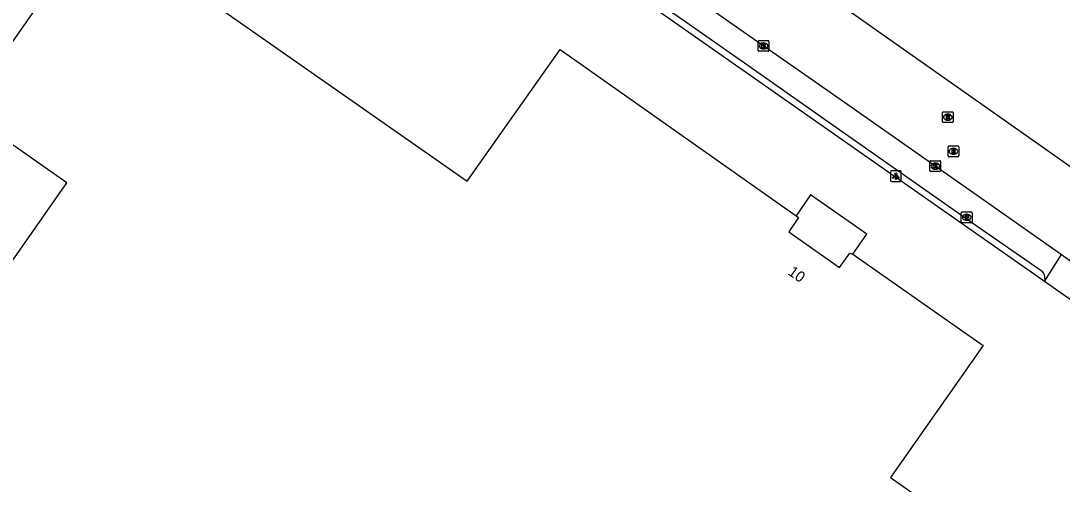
# Model space of a CAD drawing. Extents: x 155018 to 156648, y 383980 to 385733.
# Drawn here: x 155235.9 to 155332.5, y 384821.5 to 384864.6 of the extents above; entities that cross this region are included whole.
import ezdxf

# ---------------------------------------------------------------- set-up
doc = ezdxf.new("R2010")
doc.units = 0
for name, color, linetype in [('IMGEO_Brandkraan', 7, 'Continuous'), ('IMGEO_Kolk', 7, 'Continuous'), ('IMGEO_Lichtpunt', 7, 'Continuous'), ('IMGEO_Pand', 7, 'Continuous'), ('IMGEO_Pand_nummerreeks', 7, 'Continuous'), ('IMGEO_Pand_overbouw', 7, 'Continuous'), ('IMGEO_Rijbaan_lokaal_gesloten', 7, 'Continuous'), ('IMGEO_Rijbaan_lokaal_open', 7, 'Continuous'), ('IMGEO_Rioolput', 7, 'Continuous'), ('IMGEO_Voetpad_open', 7, 'Continuous')]:
    doc.layers.add(name, color=color, linetype=linetype)

msp = doc.modelspace()

# ---------------------------------------------------------------- linework, layer by layer
at = {"layer": 'IMGEO_Brandkraan'}
for p, q in [((155323.18, 384845.9), (155323.18, 384846.752)), ((155323.255, 384846.826), (155324.107, 384846.826)), ((155323.668, 384846.606), (155323.693, 384846.606)), ((155324.181, 384846.752), (155324.181, 384845.9)), ((155324.107, 384845.826), (155323.255, 384845.826)), ((155323.691, 384846.046), (155323.666, 384846.046))]:
    msp.add_line(p, q, dxfattribs=at)
for points in [[(155323.18, 384845.9), (155323.18, 384846.752)], [(155323.255, 384846.826), (155324.107, 384846.826)], [(155324.181, 384846.752), (155324.181, 384845.9)], [(155324.107, 384845.826), (155323.255, 384845.826)], [(155323.528, 384846.526), (155323.528, 384846.126), (155323.741, 384846.126)], [(155323.759, 384846.526), (155323.528, 384846.526)], [(155323.707, 384846.445), (155323.653, 384846.445), (155323.653, 384846.369)], [(155323.653, 384846.369), (155323.706, 384846.369)], [(155323.715, 384846.293), (155323.653, 384846.293), (155323.653, 384846.212)], [(155323.653, 384846.212), (155323.715, 384846.212)]]:
    msp.add_lwpolyline(points, dxfattribs=at)
for centre, radius, start, end in [((155323.257, 384846.75), 0.0765, 91.55205, 178.44795), ((155323.257, 384846.75), 0.0765, 91.55205, 178.44795), ((155324.105, 384846.75), 0.0765, 1.55205, 88.44795), ((155324.105, 384846.75), 0.0765, 1.55205, 88.44795), ((155323.257, 384845.902), 0.0765, 181.55205, 268.44795), ((155323.257, 384845.902), 0.0765, 181.55205, 268.44795), ((155323.708, 384846.407), 0.0379, 267.82845, 90.93552), ((155323.716, 384846.252), 0.0404, 269.87594, 90.50774), ((155323.747, 384846.377), 0.251, 268.66757, 293.53466), ((155323.763, 384846.381), 0.145, 59.4692, 91.53667), ((155323.788, 384846.428), 0.0922, 285.51372, 58.15012), ((155323.793, 384846.236), 0.105, 301.31148, 78.98903), ((155324.105, 384845.902), 0.0765, 271.55205, 358.44795), ((155324.105, 384845.902), 0.0765, 271.55205, 358.44795)]:
    msp.add_arc(centre, radius, start, end, dxfattribs=at)
for centre, major_axis, ratio, start_param, end_param in [((155323.667, 384846.326), (-0.387, 0.002), 0.722429, 4.712389, 7.853982), ((155323.692, 384846.326), (-0.39, 0.002), 0.717154, 1.570796, 4.712389)]:
    msp.add_ellipse(centre, major_axis=major_axis, ratio=ratio, start_param=start_param, end_param=end_param, dxfattribs=at)
at = {"layer": 'IMGEO_Kolk'}
for p, q in [((155304.331, 384861.82), (155304.331, 384862.672)), ((155304.406, 384862.746), (155305.258, 384862.746)), ((155304.819, 384862.526), (155304.844, 384862.526)), ((155305.332, 384862.672), (155305.332, 384861.82)), ((155305.258, 384861.746), (155304.406, 384861.746)), ((155304.842, 384861.966), (155304.817, 384861.966)), ((155320.265, 384850.655), (155320.265, 384851.507)), ((155320.34, 384851.581), (155321.192, 384851.581)), ((155321.266, 384851.507), (155321.266, 384850.655)), ((155321.192, 384850.581), (155320.34, 384850.581)), ((155320.776, 384850.801), (155320.751, 384850.801)), ((155320.753, 384851.361), (155320.778, 384851.361))]:
    msp.add_line(p, q, dxfattribs=at)
for points in [[(155304.331, 384861.82), (155304.331, 384862.672)], [(155304.406, 384862.746), (155305.258, 384862.746)], [(155304.652, 384862.446), (155304.775, 384862.446), (155304.775, 384862.295), (155304.905, 384862.446), (155305.069, 384862.446), (155304.923, 384862.295), (155305.076, 384862.046), (155304.924, 384862.046), (155304.839, 384862.21), (155304.775, 384862.143), (155304.775, 384862.046), (155304.652, 384862.046), (155304.652, 384862.446)], [(155305.332, 384862.672), (155305.332, 384861.82)], [(155305.258, 384861.746), (155304.406, 384861.746)], [(155320.265, 384850.655), (155320.265, 384851.507)], [(155320.34, 384851.581), (155321.192, 384851.581)], [(155321.266, 384851.507), (155321.266, 384850.655)], [(155321.192, 384850.581), (155320.34, 384850.581)], [(155320.586, 384851.281), (155320.709, 384851.281), (155320.709, 384851.13), (155320.839, 384851.281), (155321.003, 384851.281), (155320.857, 384851.13), (155321.01, 384850.881), (155320.858, 384850.881), (155320.773, 384851.045), (155320.709, 384850.978), (155320.709, 384850.881), (155320.586, 384850.881), (155320.586, 384851.281)]]:
    msp.add_lwpolyline(points, dxfattribs=at)
for centre, start, end in [((155304.408, 384862.67), 91.55205, 178.44795), ((155304.408, 384862.67), 91.55205, 178.44795), ((155305.256, 384862.67), 1.55205, 88.44795), ((155305.256, 384862.67), 1.55205, 88.44795), ((155304.408, 384861.822), 181.55205, 268.44795), ((155304.408, 384861.822), 181.55205, 268.44795), ((155305.256, 384861.822), 271.55205, 358.44795), ((155305.256, 384861.822), 271.55205, 358.44795), ((155320.342, 384851.505), 91.55205, 178.44795), ((155320.342, 384851.505), 91.55205, 178.44795), ((155321.19, 384851.505), 1.55205, 88.44795), ((155321.19, 384851.505), 1.55205, 88.44795), ((155320.342, 384850.657), 181.55205, 268.44795), ((155320.342, 384850.657), 181.55205, 268.44795), ((155321.19, 384850.657), 271.55205, 358.44795), ((155321.19, 384850.657), 271.55205, 358.44795)]:
    msp.add_arc(centre, 0.0765, start, end, dxfattribs=at)
for centre, major_axis, ratio, start_param, end_param in [((155304.818, 384862.246), (-0.387, 0.002), 0.722429, 4.712389, 7.853982), ((155304.843, 384862.246), (-0.39, 0.002), 0.717154, 1.570796, 4.712389), ((155320.752, 384851.081), (-0.387, 0.002), 0.722429, 4.712389, 7.853982), ((155320.777, 384851.081), (-0.39, 0.002), 0.717154, 1.570796, 4.712389)]:
    msp.add_ellipse(centre, major_axis=major_axis, ratio=ratio, start_param=start_param, end_param=end_param, dxfattribs=at)
at = {"layer": 'IMGEO_Lichtpunt'}
for p, q in [((155316.6, 384850.558), (155316.6, 384849.751)), ((155316.6, 384850.558), (155316.6, 384849.751)), ((155317.502, 384850.653), (155316.694, 384850.653)), ((155317.502, 384850.653), (155316.694, 384850.653)), ((155317.596, 384849.751), (155317.596, 384850.558)), ((155317.596, 384849.751), (155317.596, 384850.558)), ((155316.694, 384849.657), (155317.502, 384849.657)), ((155316.694, 384849.657), (155317.502, 384849.657))]:
    msp.add_line(p, q, dxfattribs=at)
for points in [[(155316.974, 384850.222), (155317.013, 384850.194), (155316.825, 384849.932), (155316.787, 384849.959), (155316.974, 384850.222)], [(155317.076, 384850.174), (155317.123, 384850.174), (155317.123, 384849.852), (155317.076, 384849.852), (155317.076, 384850.174)], [(155317.186, 384850.194), (155317.224, 384850.221), (155317.411, 384849.959), (155317.372, 384849.931), (155317.186, 384850.194)]]:
    msp.add_lwpolyline(points, dxfattribs=at)
msp.add_circle((155317.099, 384850.356), 0.0994, dxfattribs=at)
for centre, start, end in [((155316.694, 384850.558), 90, 180), ((155316.694, 384850.558), 90, 180), ((155317.502, 384850.558), 0, 90), ((155317.502, 384850.558), 0, 90), ((155316.694, 384849.751), 180, 270), ((155316.694, 384849.751), 180, 270), ((155317.502, 384849.751), 270, 0), ((155317.502, 384849.751), 270, 360)]:
    msp.add_arc(centre, 0.0946, start, end, dxfattribs=at)
at = {"layer": 'IMGEO_Pand'}
msp.add_lwpolyline([(155307.854, 384846.467), (155308.084, 384846.304), (155307.162, 384844.985), (155311.873, 384841.65), (155312.842, 384843.004), (155313.123, 384842.891), (155325.2, 384834.412), (155316.62, 384822.15), (155331.369, 384811.803), (155328.502, 384807.708), (155294.79, 384759.56), (155206.342, 384821.5), (155218.64, 384839.075), (155228.194, 384832.391), (155240.179, 384849.519), (155230.625, 384856.203), (155240.044, 384869.665), (155242.91, 384873.761), (155277.333, 384849.672), (155285.969, 384861.914), (155307.854, 384846.467)], dxfattribs=at)
at = {"layer": 'IMGEO_Pand_overbouw'}
msp.add_lwpolyline([(155307.854, 384846.467), (155308.084, 384846.304), (155307.162, 384844.985), (155311.873, 384841.65), (155312.842, 384843.004), (155313.123, 384842.891), (155314.41, 384844.769), (155309.184, 384848.411)], close=True, dxfattribs=at)
at = {"layer": 'IMGEO_Rijbaan_lokaal_gesloten'}
for points in [[(155282.705, 384877.749), (155304.661, 384862.364), (155312.349, 384857.014), (155325.715, 384847.641), (155332.492, 384842.858)], [(155339.386, 384846.829), (155338.759, 384847.187), (155308.812, 384868.307)], [(155332.492, 384842.858), (155336.825, 384839.821)]]:
    msp.add_lwpolyline(points, dxfattribs=at)
at = {"layer": 'IMGEO_Rijbaan_lokaal_open'}
for points in [[(155330.905, 384840.366), (155332.492, 384842.858)], [(155335.262, 384837.311), (155330.905, 384840.366)]]:
    msp.add_lwpolyline(points, dxfattribs=at)
at = {"layer": 'IMGEO_Rioolput'}
for p, q in [((155321.431, 384855.202), (155321.431, 384856.054)), ((155321.506, 384856.128), (155322.358, 384856.128)), ((155321.942, 384855.348), (155321.917, 384855.348)), ((155321.919, 384855.908), (155321.944, 384855.908)), ((155322.432, 384856.054), (155322.432, 384855.202)), ((155322.358, 384855.128), (155321.506, 384855.128)), ((155321.951, 384852.032), (155321.951, 384852.884)), ((155322.026, 384852.958), (155322.878, 384852.958)), ((155322.439, 384852.738), (155322.464, 384852.738)), ((155322.952, 384852.884), (155322.952, 384852.032)), ((155322.878, 384851.958), (155322.026, 384851.958)), ((155322.462, 384852.178), (155322.437, 384852.178))]:
    msp.add_line(p, q, dxfattribs=at)
for points in [[(155321.431, 384855.202), (155321.431, 384856.054)], [(155321.506, 384856.128), (155322.358, 384856.128)], [(155322.02, 384855.826), (155321.768, 384855.828), (155321.768, 384855.428)], [(155321.768, 384855.428), (155321.892, 384855.428), (155321.892, 384855.59), (155321.903, 384855.59)], [(155321.946, 384855.747), (155321.892, 384855.747), (155321.892, 384855.666)], [(155321.892, 384855.666), (155321.944, 384855.666)], [(155321.95, 384855.561), (155322.021, 384855.428), (155322.161, 384855.428), (155322.096, 384855.554)], [(155322.432, 384856.054), (155322.432, 384855.202)], [(155322.358, 384855.128), (155321.506, 384855.128)], [(155321.951, 384852.032), (155321.951, 384852.884)], [(155322.026, 384852.958), (155322.878, 384852.958)], [(155322.54, 384852.656), (155322.288, 384852.658), (155322.288, 384852.258)], [(155322.288, 384852.258), (155322.412, 384852.258), (155322.412, 384852.42), (155322.423, 384852.42)], [(155322.466, 384852.577), (155322.412, 384852.577), (155322.412, 384852.496)], [(155322.412, 384852.496), (155322.464, 384852.496)], [(155322.952, 384852.884), (155322.952, 384852.032)], [(155322.878, 384851.958), (155322.026, 384851.958)], [(155322.47, 384852.391), (155322.541, 384852.258), (155322.681, 384852.258), (155322.616, 384852.384)]]:
    msp.add_lwpolyline(points, dxfattribs=at)
for centre, radius, start, end in [((155321.508, 384856.052), 0.0765, 91.55205, 178.44795), ((155321.508, 384856.052), 0.0765, 91.55205, 178.44795), ((155321.902, 384855.537), 0.0533, 26.02933, 88.69889), ((155321.928, 384855.855), 0.19, 274.7715, 282.96867), ((155321.952, 384855.651), 0.0964, 77.00612, 93.18647), ((155321.966, 384855.708), 0.0378, 276.66336, 79.67722), ((155322.019, 384855.716), 0.109, 350.36119, 89.41601), ((155322.017, 384855.716), 0.112, 277.58423, 350.98172), ((155322.001, 384855.501), 0.108, 29.51342, 73.79051), ((155322.356, 384856.052), 0.0765, 1.55205, 88.44795), ((155322.356, 384856.052), 0.0765, 1.55205, 88.44795), ((155321.508, 384855.204), 0.0765, 181.55205, 268.44795), ((155321.508, 384855.204), 0.0765, 181.55205, 268.44795), ((155322.356, 384855.204), 0.0765, 271.55205, 358.44795), ((155322.356, 384855.204), 0.0765, 271.55205, 358.44795), ((155322.028, 384852.882), 0.0765, 91.55205, 178.44795), ((155322.028, 384852.882), 0.0765, 91.55205, 178.44795), ((155322.422, 384852.367), 0.0533, 26.02933, 88.69889), ((155322.448, 384852.685), 0.19, 274.7715, 282.96867), ((155322.472, 384852.481), 0.0964, 77.00612, 93.18647), ((155322.486, 384852.538), 0.0378, 276.66336, 79.67722), ((155322.539, 384852.546), 0.109, 350.36119, 89.41601), ((155322.537, 384852.546), 0.112, 277.58423, 350.98172), ((155322.521, 384852.331), 0.108, 29.51342, 73.79051), ((155322.876, 384852.882), 0.0765, 1.55205, 88.44795), ((155322.876, 384852.882), 0.0765, 1.55205, 88.44795), ((155322.028, 384852.034), 0.0765, 181.55205, 268.44795), ((155322.028, 384852.034), 0.0765, 181.55205, 268.44795), ((155322.876, 384852.034), 0.0765, 271.55205, 358.44795), ((155322.876, 384852.034), 0.0765, 271.55205, 358.44795)]:
    msp.add_arc(centre, radius, start, end, dxfattribs=at)
for centre, major_axis, ratio, start_param, end_param in [((155321.918, 384855.628), (-0.387, 0.002), 0.722429, 4.712389, 7.853982), ((155321.943, 384855.628), (-0.39, 0.002), 0.717154, 1.570796, 4.712389), ((155322.438, 384852.458), (-0.387, 0.002), 0.722429, 4.712389, 7.853982), ((155322.463, 384852.458), (-0.39, 0.002), 0.717154, 1.570796, 4.712389)]:
    msp.add_ellipse(centre, major_axis=major_axis, ratio=ratio, start_param=start_param, end_param=end_param, dxfattribs=at)
at = {"layer": 'IMGEO_Voetpad_open'}
for points in [[(155330.905, 384840.366), (155281.186, 384875.226)], [(155282.214, 384875.28), (155303.376, 384860.446), (155310.968, 384855.094), (155324.356, 384845.722), (155330.672, 384841.312)], [(155330.944, 384840.604), (155330.905, 384840.366)]]:
    msp.add_lwpolyline(points, dxfattribs=at)
msp.add_arc((155330.172, 384840.714), 0.78, 351.91448, 50.11715, dxfattribs=at)

# ---------------------------------------------------------------- texts
at = {"layer": 'IMGEO_Pand_nummerreeks'}
msp.add_text('10', height=1, rotation=324.70465, dxfattribs=at).set_placement((155307.025, 384841.064))

doc.saveas('drawing.dxf')
